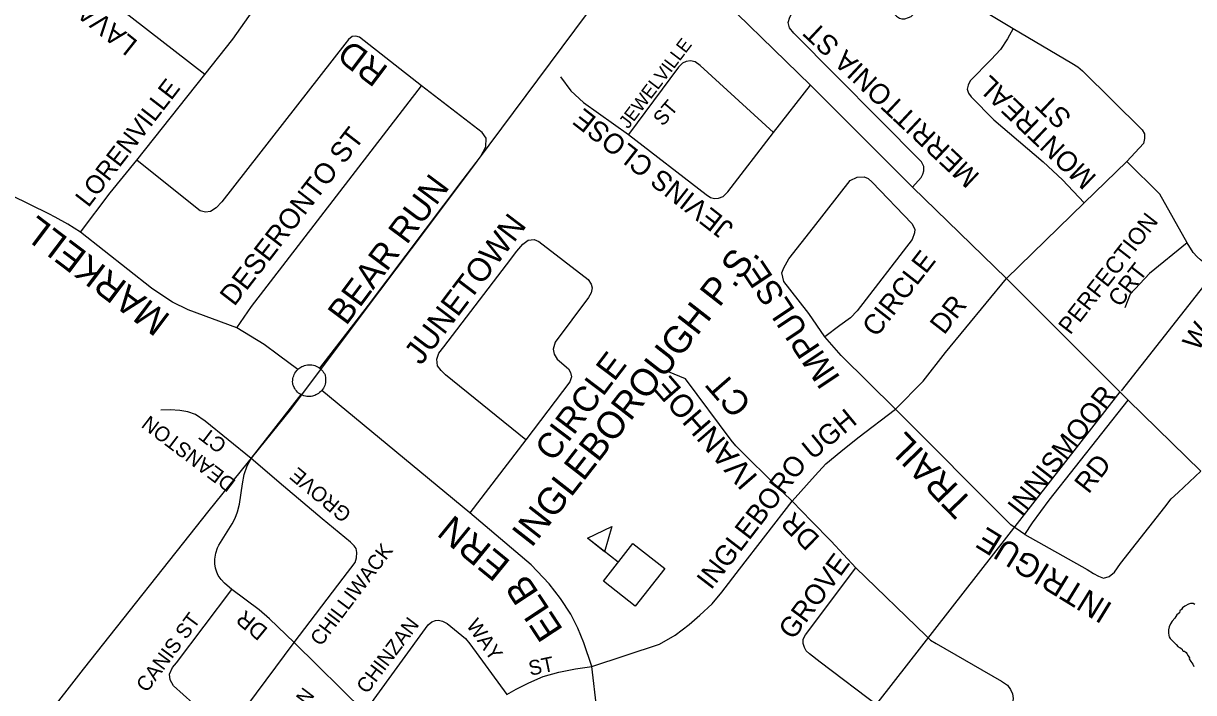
# Model space of a CAD drawing. Extents: x 586326 to 623965, y 4819854 to 4857850.
# Drawn here: x 595922 to 597005, y 4834619 to 4835238 of the extents above; entities that cross this region are included whole.
import ezdxf

# ---------------------------------------------------------------- set-up
doc = ezdxf.new("R2010")
doc.units = 0
for name, color, linetype in [('Lots_Concessions', 7, 'Continuous'), ('Minor Rd Lbls', 7, 'Continuous'), ('Minor Rds', 7, 'Continuous'), ('Proposed Secondary Rds', 7, 'Continuous'), ('School Syms_Lbls', 7, 'Continuous'), ('Secondary Rds Lbls', 7, 'Continuous'), ('SWM Ponds', 7, 'Continuous')]:
    doc.layers.add(name, color=color, linetype=linetype)

msp = doc.modelspace()

# ---------------------------------------------------------------- linework, layer by layer
at = {"layer": 'Lots_Concessions'}
for p, q in [((596330.9, 4835095.3), (596503.9, 4835327.6)), ((596938.7, 4834898.2), (597268.2, 4835316.8)), ((596295.9, 4835048.5), (596335.2, 4835101.2)), ((596238.2, 4834971.8), (596295.9, 4835048.5)), ((596169.9, 4834880.8), (596238.2, 4834971.8)), ((596522.5, 4834364.9), (596937.4, 4834897.3)), ((596094.4, 4834787.4), (596169.9, 4834880.8)), ((595978.2, 4834640.5), (596094.4, 4834787.4)), ((595682.8, 4834264.2), (595978.2, 4834640.5))]:
    msp.add_line(p, q, dxfattribs=at)
at = {"layer": 'Minor Rds'}
for points in [[(596090.3, 4835190.8), (595943.4, 4835304.9), (595940.4, 4835308.8), (595940, 4835312.6), (595940.2, 4835316.5), (595941.8, 4835320.4), (595976.8, 4835365.7), (595980.3, 4835368.7), (595984.3, 4835370.1), (595988.7, 4835370.3), (595993.4, 4835367.6), (596138.5, 4835255.1)], [(596745.3, 4835086.7), (596753.2, 4835095.5), (596755, 4835098.5), (596755.8, 4835101.8), (596755.8, 4835105.7), (596753.8, 4835109.9), (596635.5, 4835229.1), (596631.6, 4835234), (596630.2, 4835239), (596631.7, 4835244), (596633.8, 4835247.3), (596679, 4835294.4)], [(596679, 4835294.4), (596730.4, 4835244.9), (596733.2, 4835243), (596735.6, 4835242.4), (596738.2, 4835242.3), (596741.5, 4835243.5), (596744.1, 4835244.5), (596767.6, 4835267.8), (596771.2, 4835269.7), (596775, 4835270.2), (596780.6, 4835268.5), (596838.5, 4835233.5)], [(596090.3, 4835190.8), (596116.3, 4835223.5), (596138.5, 4835255.1)], [(596290.9, 4835180.5), (596233.4, 4835225.4), (596230, 4835226.3), (596226.6, 4835225.9), (596223.3, 4835223.2), (596219.9, 4835218.9), (596106, 4835073), (596101, 4835067.5), (596095.5, 4835064), (596091.1, 4835063.4), (596086.1, 4835064.7), (596081.8, 4835068), (596027.3, 4835111.6)], [(596838.5, 4835233.5), (596833.2, 4835224), (596826.8, 4835214.1), (596818, 4835204.6), (596798.7, 4835185), (596796.7, 4835181), (596796, 4835177.3), (596797.2, 4835173.5), (596799.6, 4835170.2), (596820.7, 4835148.8), (596866.2, 4835110.1), (596884.2, 4835093.4), (596904.3, 4835072)], [(596838.5, 4835233.5), (596892.7, 4835201.5), (596898.2, 4835198.1), (596902.8, 4835194.2), (596957.8, 4835139.8), (596959.9, 4835136.1), (596960.1, 4835131.7), (596959.2, 4835127.1), (596943.6, 4835110.2)], [(596616.7, 4835137.1), (596548.7, 4835199.3), (596544.2, 4835202.7), (596539.9, 4835203.4), (596535.8, 4835202.8), (596532.4, 4835201.5), (596528.8, 4835197.7), (596482.4, 4835135.2)], [(596027.3, 4835111.6), (596090.3, 4835190.8)], [(596119.9, 4834956.3), (596133.5, 4834976.2), (596290.9, 4835180.5)], [(596241.7, 4834977.4), (596329.4, 4835093.8), (596345.6, 4835114.8), (596350.3, 4835123.8), (596350.6, 4835131.9), (596347.1, 4835137.2), (596290.9, 4835180.5)], [(596419.4, 4835188.7), (596429, 4835175.7), (596440.7, 4835165), (596482.4, 4835135.2)], [(596616.7, 4835137.1), (596651, 4835181.1)], [(596482.4, 4835135.2), (596554.4, 4835079.7), (596558.5, 4835077.1), (596562.1, 4835076.1), (596565.8, 4835076.3), (596570.2, 4835078.1), (596574.4, 4835082.2), (596616.7, 4835137.1)], [(595975.3, 4835045), (596002.9, 4835081.4), (596027.3, 4835111.6)], [(596943.6, 4835110.2), (596904.3, 4835072)], [(596999.5, 4835035.2), (596974.3, 4835080), (596943.6, 4835110.2)], [(596687.6, 4835092.7), (596694.2, 4835095.8), (596700.5, 4835096.3), (596704.4, 4835094.5), (596708.1, 4835091.2), (596744.8, 4835053.1), (596747.5, 4835047.8), (596747.3, 4835044.3), (596745, 4835038.3), (596694.2, 4834972.3), (596688, 4834965.7), (596678.2, 4834958.5), (596664.2, 4834948)], [(596664.2, 4834948), (596649.3, 4834969.6), (596631.8, 4834992.3), (596626.4, 4834999.3), (596624.4, 4835007.2), (596626.3, 4835012), (596630.9, 4835020.2), (596653.8, 4835049.4), (596687.6, 4835092.7)], [(596904.3, 4835072), (596832.2, 4835002)], [(596369.5, 4835014.8), (596379.1, 4835027.4), (596384.6, 4835034), (596389.5, 4835037.5), (596395.2, 4835038.2), (596399.6, 4835036.2), (596445.1, 4835001.1), (596447.9, 4834996.8), (596448.9, 4834993.4), (596447.9, 4834988.9), (596445.5, 4834984.4), (596414.6, 4834943.1), (596412.9, 4834936.8), (596413.8, 4834932.1), (596416.5, 4834927.4), (596427.1, 4834918.5), (596428.8, 4834915.1), (596429.6, 4834911.2), (596428.3, 4834906.3), (596387.4, 4834852.8)], [(596999.5, 4835035.2), (596964.8, 4835006.6), (596946.8, 4834987.6), (596941.9, 4834975)], [(597025.8, 4835008.3), (597012, 4835019.4), (597008.8, 4835022.2), (597005.2, 4835026), (596999.5, 4835035.2)], [(596387.4, 4834852.8), (596313, 4834912.8), (596309, 4834916.9), (596305.7, 4834921.4), (596305, 4834927.3), (596307, 4834932.9), (596311.7, 4834938.9), (596369.5, 4835014.8)], [(596196.9, 4834919), (596241.7, 4834977.4)], [(596729.5, 4834881.3), (596679.4, 4834930.7), (596664.2, 4834948)], [(596625.2, 4834804.4), (596623, 4834806.6), (596581.8, 4834847.2), (596577.6, 4834852.5), (596535.1, 4834909.1), (596519.4, 4834915.8)], [(596133.1, 4834835.4), (596179.5, 4834894.7)], [(596849.4, 4834765.1), (596856.4, 4834775.9), (596871.7, 4834797), (596944.9, 4834889.4)], [(596133.1, 4834835.4), (596090.6, 4834870.1), (596081.7, 4834876.1), (596074.6, 4834878.8), (596067.1, 4834880), (596058.4, 4834880.6), (596049.5, 4834880.3)], [(596849.4, 4834765.1), (596836.3, 4834774.1), (596729.5, 4834881.3)], [(596387.4, 4834852.8), (596335.5, 4834785.2)], [(596115.5, 4834714.3), (596108.5, 4834720.1), (596105.4, 4834723.6), (596102.8, 4834727.3), (596101.4, 4834730.3), (596100.2, 4834734), (596099.7, 4834738.1), (596099.7, 4834742.5), (596100.5, 4834747.8), (596102, 4834752.7), (596103.2, 4834755.2), (596115.8, 4834774.9), (596118.3, 4834780.3), (596120.5, 4834786), (596122.6, 4834793.1), (596125.1, 4834812.2), (596126.9, 4834820.7), (596129.6, 4834828.6), (596133.1, 4834835.4)], [(596173.2, 4834665.1), (596218.4, 4834724.9), (596229.4, 4834739.2), (596230.8, 4834743.6), (596230.9, 4834748.4), (596230.3, 4834752.1), (596228.7, 4834754.7), (596225.2, 4834758), (596199, 4834779.8), (596163.1, 4834809.8), (596133.1, 4834835.4)], [(596849.4, 4834765.1), (596907, 4834732.8), (596912.8, 4834729.1), (596917.6, 4834726.6), (596922.1, 4834724.8), (596927.2, 4834726.2), (596932.2, 4834730.2), (596937.9, 4834738.2), (596978.8, 4834790.4), (596984.8, 4834798.1), (596991.1, 4834804.1), (597012.1, 4834823.9)], [(596634, 4834795.9), (596625.2, 4834804.4)], [(596634, 4834795.9), (596652, 4834777.5)], [(596652, 4834777.5), (596670.1, 4834759), (596692.9, 4834734.2)], [(596714.6, 4834605.7), (596660, 4834647), (596650, 4834654.6), (596647, 4834657.6), (596645.4, 4834660.5), (596644, 4834664.2), (596644.1, 4834668.2), (596646.3, 4834672.2), (596692.9, 4834734.2)], [(596692.9, 4834734.2), (596757.9, 4834671.5), (596762.1, 4834667.4), (596767.1, 4834664.3), (596827.8, 4834629.3), (596833.4, 4834625.6), (596836.1, 4834621.6), (596837.8, 4834617.7), (596838.5, 4834613.3), (596838, 4834609.3), (596835.9, 4834604.9), (596758.7, 4834505.1), (596755.8, 4834500), (596753.3, 4834493.6), (596751.8, 4834486.4), (596746.1, 4834443.2)], [(596112.3, 4834583.5), (596088.2, 4834601.2), (596061.3, 4834625.2), (596058.2, 4834630.6), (596057.8, 4834636), (596060.4, 4834642), (596064, 4834646.3), (596115.5, 4834714.3)], [(596173.2, 4834665.1), (596150.1, 4834687.2), (596140.7, 4834695.6), (596115.5, 4834714.3)], [(596244.6, 4834609.4), (596297.1, 4834681.7), (596300.4, 4834684.3), (596303.9, 4834685.7), (596306.7, 4834686), (596310.3, 4834685.1), (596314.7, 4834682.7), (596331.6, 4834668.8), (596335.7, 4834664.1), (596370, 4834617)], [(596112.3, 4834583.5), (596173.2, 4834665.1)], [(596238.1, 4834601.1), (596173.2, 4834665.1)], [(596370, 4834617), (596378.4, 4834622.1), (596390.2, 4834627.9), (596403.6, 4834633.7), (596418.1, 4834637.7), (596433.3, 4834641), (596448.6, 4834643)]]:
    msp.add_lwpolyline(points, dxfattribs=at)
at = {"layer": 'Proposed Secondary Rds'}
for points in [[(596651, 4835181.1), (596548.8, 4835280.7)], [(596745.3, 4835086.7), (596651, 4835181.1)], [(595975.3, 4835045), (595963.7, 4835052.5), (595952, 4835058.8), (595946.1, 4835062), (595911.3, 4835079), (595910.2, 4835079.5), (595897.4, 4835086.2), (595851.3, 4835117.4), (595787.1, 4835167.2)], [(596832.2, 4835002), (596745.3, 4835086.7)], [(596119.9, 4834956.3), (596074.9, 4834973), (596060.3, 4834980.3), (596050.5, 4834986.6), (596040.9, 4834993.2), (595975.3, 4835045)], [(596775.8, 4834933.5), (596832.2, 4835002)], [(596944.9, 4834889.4), (596832.2, 4835002)], [(596176.4, 4834917.9), (596158.5, 4834931.2), (596145.2, 4834941.1), (596119.9, 4834956.3)], [(596729.5, 4834881.3), (596755.1, 4834907), (596775.8, 4834933.5)], [(596176.4, 4834917.9), (596177.3, 4834918.7), (596178.2, 4834919.4), (596179.2, 4834920), (596180.2, 4834920.6), (596181.3, 4834921.1), (596182.6, 4834921.5), (596183.9, 4834921.9), (596185.3, 4834922.1), (596186.7, 4834922.2), (596188.1, 4834922.2), (596189.4, 4834922.1), (596190.8, 4834921.8), (596192.1, 4834921.5), (596193.4, 4834921), (596194.7, 4834920.4), (596195.8, 4834919.7), (596196.9, 4834919)], [(596179.5, 4834894.7), (596178.3, 4834895.4), (596177.2, 4834896.1), (596176.2, 4834897), (596175.2, 4834898), (596174.3, 4834899), (596173.6, 4834900.2), (596172.9, 4834901.3), (596172.3, 4834902.6), (596171.9, 4834903.9), (596171.7, 4834905.2), (596171.6, 4834906.6), (596171.7, 4834908), (596171.9, 4834909.4), (596172.2, 4834910.7), (596172.6, 4834912), (596173.1, 4834913.3), (596173.8, 4834914.5), (596174.5, 4834915.7), (596175.4, 4834916.8), (596175.9, 4834917.4), (596176.4, 4834917.9)], [(596196.9, 4834919), (596197.8, 4834918.1), (596198.8, 4834917.2), (596199.6, 4834916.3), (596200.3, 4834915.2), (596201, 4834914.2), (596201.6, 4834913), (596201.8, 4834912), (596202, 4834910.9), (596202.2, 4834909.8), (596202.2, 4834908.5), (596202.2, 4834907.1), (596202, 4834905.8), (596201.7, 4834904.4), (596201.3, 4834903.1), (596200.8, 4834901.9), (596200.2, 4834900.7), (596199.4, 4834899.5), (596198.6, 4834898.4)], [(596198.6, 4834898.4), (596197.7, 4834897.4), (596196.6, 4834896.5), (596195.5, 4834895.7), (596194.4, 4834894.9), (596193.2, 4834894.3), (596192.1, 4834893.9), (596191, 4834893.5), (596190, 4834893.2), (596188.9, 4834893), (596187.5, 4834892.9), (596186.1, 4834892.9), (596184.7, 4834893), (596183.4, 4834893.3), (596182, 4834893.6), (596180.8, 4834894.1), (596179.5, 4834894.7)], [(596335.5, 4834785.2), (596198.6, 4834898.4)], [(597012.1, 4834823.9), (596944.9, 4834889.4)], [(596634, 4834795.9), (596655.1, 4834819.9), (596665.2, 4834830.5), (596678.9, 4834842.1), (596694.8, 4834854.5), (596729.5, 4834881.3)], [(596448.6, 4834643), (596511.3, 4834663.6), (596525.7, 4834672.1), (596538.5, 4834681.9), (596548.6, 4834690.4), (596559.9, 4834701.1), (596568.8, 4834711.8), (596585.3, 4834733.1), (596634, 4834795.9)], [(596448.6, 4834643), (596441.1, 4834664.9), (596435.6, 4834678.4), (596429.2, 4834691.4), (596419.6, 4834705.9), (596409.1, 4834719.5), (596392.5, 4834737.1), (596335.5, 4834785.2)], [(596453.9, 4834522), (596452.8, 4834534.4), (596452.8, 4834563.9), (596453.2, 4834603.4), (596448.6, 4834643)]]:
    msp.add_lwpolyline(points, dxfattribs=at)
at = {"layer": 'School Syms_Lbls'}
msp.add_line((596472.8, 4834739.5), (596444.4, 4834761.7), dxfattribs=at)
for points in [[(596444.4, 4834761.7), (596467.2, 4834772.7), (596460.3, 4834749.2)], [(596459.2, 4834722), (596486.5, 4834756.9), (596516.1, 4834733.8), (596488.8, 4834698.9)]]:
    msp.add_lwpolyline(points, close=True, dxfattribs=at)
at = {"layer": 'SWM Ponds'}
msp.add_lwpolyline([(597006.5, 4834700.4), (597005.1, 4834701.2), (597002.7, 4834701.2), (597000.8, 4834700.7), (596997.5, 4834698.9), (596995.2, 4834697.2), (596994.2, 4834695.8), (596992.8, 4834694.6), (596992.4, 4834692.8), (596990, 4834690.7), (596988, 4834687.9), (596985.7, 4834685.1), (596984.1, 4834682.6), (596982.8, 4834679.7), (596982.2, 4834676.8), (596982.3, 4834674.3), (596982.6, 4834671.8), (596983, 4834670.5), (596983.8, 4834669), (596985, 4834667.7), (596987, 4834665.7), (596989.3, 4834663.4), (596991.1, 4834661.2), (596992.9, 4834660.7), (596994.1, 4834659.8), (596994.8, 4834659), (596995.2, 4834657.9), (596995.9, 4834657.1), (596997, 4834657.3), (596998.5, 4834655.9), (596999.2, 4834655), (597000.4, 4834652.9), (597001.7, 4834651.1), (597001.5, 4834650.1), (597002.8, 4834647.5), (597004.9, 4834645.2), (597005.7, 4834642.9)], dxfattribs=at)

# ---------------------------------------------------------------- texts
at = {"layer": 'Minor Rd Lbls'}
for s, height, rotation, p in [('LAVALLEE', 17.94, 141.5123, (596029.3, 4835221.2)), ('MERRITTONIA ST', 18.529, 136.8524, (596808.5, 4835097.9)), ('JEWELVILLE', 12.16, 52.782, (596482.2, 4835140)), ('RD', 23.45, 142.9179, (596261.3, 4835196.9)), ('MONTREAL', 18.53, 136.3867, (596916.6, 4835096.4)), ('LORENVILLE', 17.02, 52.3287, (595982.6, 4835067.1)), ('ST', 18.53, 136.3867, (596893.7, 4835152.3)), ('JEVINS CLOSE', 18.529, 142.0016, (596580.9, 4835051.2)), ('ST', 13.51, 49.745, (596514.3, 4835142.3)), ('DESERONTO ST', 18.78, 52.3287, (596117.6, 4834975.6)), ('BEAR RUN', 23.31, 53.223, (596221.2, 4834957.7)), ('JUNETOWN', 21.54, 52.8741, (596290.4, 4834921)), ('PERFECTION', 15.53, 52.0883, (596891.3, 4834949.3)), ('CIRCLE', 18.53, 52.0883, (596711.9, 4834946.9)), ('IMPULSE', 22.54, 123.7142, (596679.2, 4834910.1)), ('CRT', 15.53, 52.0883, (596937.3, 4834974.8)), ('W', 18.5, 57.856, (597009.8, 4834933.9)), ('CIRCLE', 23.31, 52.8741, (596412.8, 4834831.4)), ('IVANHOE', 20.98, 130.9728, (596603.2, 4834818.3)), ('CT', 23.16, 130.9728, (596597.5, 4834886.4)), ('INNISMOOR', 18.53, 52.0883, (596846.5, 4834780.8)), ('DEANSTON', 13.69, 142.7466, (596119.9, 4834814.5)), ('CT', 13.69, 142.7466, (596111.7, 4834850.2)), ('TRAIL', 24.38, 134.0138, (596802.7, 4834795.2)), ('RD', 18.53, 52.0883, (596908.3, 4834802)), ('GROVE', 13.69, 140.0049, (596227.1, 4834785.7)), ('DR', 18.53, 135.5685, (596660.6, 4834762.2)), ('INTRIGUE', 21.68, 148.3856, (596931.6, 4834700.3)), ('CHILLIWACK', 13.69, 52.9473, (596197.7, 4834661)), ('GROVE', 18.53, 53.3744, (596634.8, 4834666.8)), ('CANIS ST', 13.69, 53.5069, (596036.7, 4834618.2)), ('DR', 15.01, 140.388, (596149.7, 4834677.6)), ('CHINZAN', 13.69, 52.9473, (596240.4, 4834616.9)), ('WAY', 13.69, 305.1813, (596331.8, 4834681.1)), ('ST', 13.69, 11.6274, (596391.5, 4834634.4)), ('CANNINGTON', 13.69, 52.9473, (596118.5, 4834518.3))]:
    msp.add_text(s, height=height, rotation=rotation, dxfattribs=at).set_placement(p)
at = {"layer": 'School Syms_Lbls'}
msp.add_text('INGLEBOROUGH P.S.', height=25, rotation=52, dxfattribs=at).set_placement((596392.6, 4834752.1))
at = {"layer": 'Secondary Rds Lbls'}
for s, height, rotation, p in [('MARKELL', 25, 142.9179, (596059.7, 4834967.3)), ('DR', 18.53, 52.0883, (596774.6, 4834949.2)), ('UGH', 18.53, 39.4267, (596652.8, 4834833.6)), ('INGLEBORO', 18.53, 52.5308, (596558.9, 4834713.2)), ('ERN', 25, 140.7866, (596374.5, 4834739.7)), ('ELB', 25, 123.3311, (596422.5, 4834677))]:
    msp.add_text(s, height=height, rotation=rotation, dxfattribs=at).set_placement(p)

doc.saveas('drawing.dxf')
